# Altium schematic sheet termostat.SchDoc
size A4
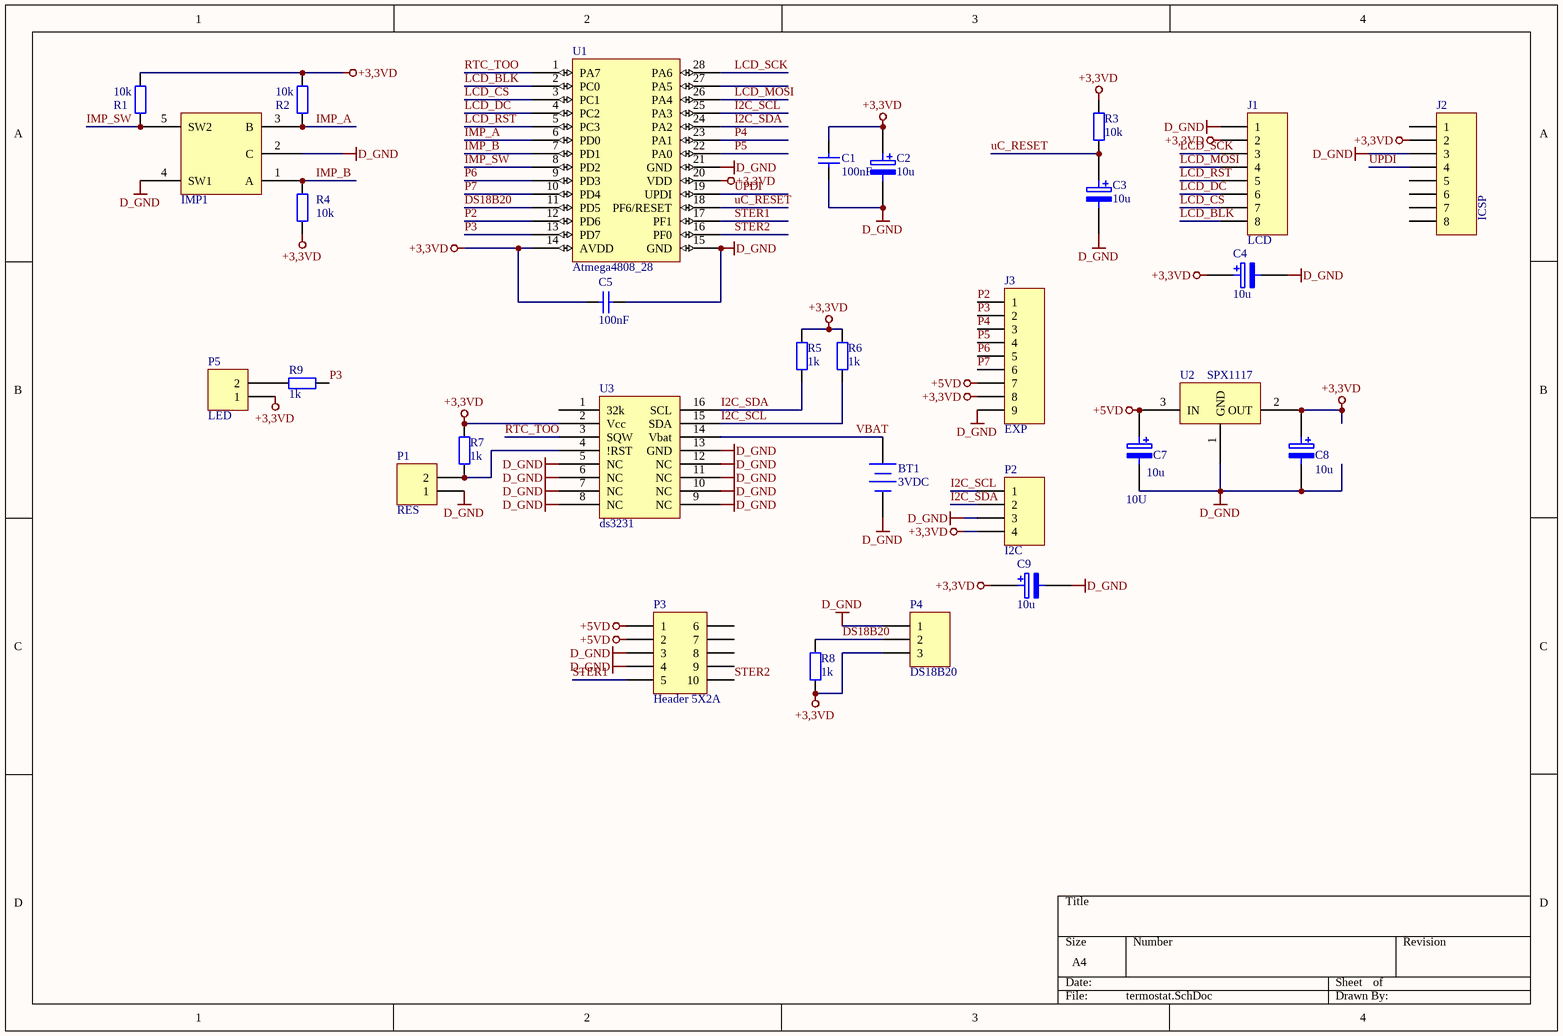
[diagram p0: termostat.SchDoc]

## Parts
BT1  3VDC  [BAT]
C1  100nF  [1206]
C2  10u  [3528]
C3  10u  [3528]
C4  10u  [3528]
C5  value 100nF  [1206]  (hidden comment: Cap)
C7  10u  [3528]
C8  10u  [3528]
C9  10u  [3528]
IMP1  IMP_PIHER  [IMP_PIHER]  (value not drawn)
J1  LCD  [lcd_128_160]
J2  ICSP  [HDR1X8]
J3  EXP  [HDR1X9]
P1  RES  [HDR1X2]
P2  I2C  [HDR1X4]
P3  Header 5X2A  [HDR2X5_CEN]
P4  DS18B20  [HDR1X3]
P5  LED  [HDR1X2]
R1  value 10k  [1206]
R2  value 10k  [1206]
R3  10k  [1206]
R4  value 10k  [1206]
R5  1k  [1206]
R6  1k  [1206]
R7  1k  [1206]
R8  1k  [1206]
R9  1k  [1206]
U1  Atmega4808_28  [atmega4808_28 - duplicate]
U2  SPX1117  [to252-3l]
U3  ds3231  [DS3231]

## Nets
+3,3VD: C1.1 C2.1 C4.1 C5.2 C8.1 C9.1 J1.2 J2.2 J3.8 P2.4 P4.3 P5.1 R1.1 R2.1 R3.2 R4.1 R5.2 R6.1 R7.1 R8.1 U1.14(AVDD) U1.20(VDD) U2.2(OUT) U3.2(Vcc)
+5VD: C7.1 J3.7 P3.1 P3.2 U2.3(IN)
D_GND: BT1.2(-) C1.2 C2.2 C3.2 C4.2 C5.1 C7.2 C8.2 C9.2 IMP1.2(C) IMP1.4(SW1) J1.1 J2.3 J3.9 P1.1 P2.3 P3.3 P3.4 P4.1 U1.15(GND) U1.21(GND) U2.1(GND) U3.5(NC) U3.6(NC) U3.7(NC) U3.8(NC) U3.9(NC) U3.10(NC) U3.11(NC) U3.12(NC) U3.13(GND)
DS18B20: P4.2 R8.2 U1.11(PD5)
I2C_SCL: P2.1 R6.2 U1.25(PA3) U3.15(SDA)
I2C_SDA: P2.2 R5.1 U1.24(PA2) U3.16(SCL)
IMP_A: IMP1.3(B) R2.2 U1.6(PD0)
IMP_B: IMP1.1(A) R4.2 U1.7(PD1)
IMP_SW: IMP1.5(SW2) R1.2 U1.8(PD2)
LCD_BLK: J1.8 U1.2(PC0)
LCD_CS: J1.7 U1.3(PC1)
LCD_DC: J1.6 U1.4(PC2)
LCD_MOSI: J1.4 U1.26(PA4)
LCD_RST: J1.5 U1.5(PC3)
LCD_SCK: J1.3 U1.28(PA6)
P2: J3.1 U1.12(PD6)
P3: J3.2 R9.2 U1.13(PD7)
P4: J3.3 U1.23(PA1)
P5: J3.4 U1.22(PA0)
P6: J3.5 U1.9(PD3)
P7: J3.6 U1.10(PD4)
RTC_TOO: U1.1(PA7) U3.3(SQW)
STER1: P3.5 U1.17(PF1)
STER2: P3.10 U1.16(PF0)
uC_RESET: C3.1 R3.1 U1.18(PF6/RESET)
UPDI: J2.4 U1.19(UPDI)
VBAT: BT1.1(+) U3.14(Vbat)
NetP1_2: P1.2 R7.2 U3.4(!RST)
NetP5_2: P5.2 R9.1

Not connected (* = marked no-connect by the designer): J2 1 5 6 7 8; P3 6 7 8 9; U1 27(PA5); U3 1(32k)

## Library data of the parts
BT1 = Battery: Multicell Battery
C1 C5 = Cap: Capacitor
C2-C4 C7-C9 = ELECTRO2: Electrolytic Capacitor
J1 J2 = Header 8: Header, 8-Pin
J3 = Header 9: Header, 9-Pin
P1 P5 = Header 2: Header, 2-Pin
P2 = Header 4: Header, 4-Pin
P3 = Header 5X2A: Header, 5-Pin, Dual row
P4 = Header 3: Header, 3-Pin
R1-R9 = Res2: Resistor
